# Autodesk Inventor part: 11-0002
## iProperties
Created: 2007-02
Part Number: 11-0002
Material: Al CU Mg 4
Document SubType Name: Modeling
Designer: GG5883
Description: Support mors mobile brut
Author: Gilles GLEMAREC
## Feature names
1. Extrusion1
2. Extrusion2
3. Extrusion3
4. Extrusion4
5. Extrusion5
6. Miroir2 [Mirror]
7. Dépouille de face1
8. Dépouille de face2
9. Extrusion6
10. Miroir3 [Mirror]
11. Dépouille de face3
12. Scission1
13. Dépouille de face4
14. Dépouille de face5
15. Congé1 [Fillet]
16. Congé2 [Fillet]
17. Congé4 [Fillet]
18. Congé5 [Fillet]
19. Congé6 [Fillet]
20. Congé7 [Fillet]
